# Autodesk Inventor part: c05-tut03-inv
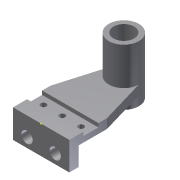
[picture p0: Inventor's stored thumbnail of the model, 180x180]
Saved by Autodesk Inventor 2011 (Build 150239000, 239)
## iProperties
Created: 2010-02
Part Number: c05-tut03-inv
Document SubType Name: Modeling
Designer: CADSoft
Density: 1 g/cm^3
Author: CADSoft
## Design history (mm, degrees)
sketch "Sketch1"
  geometry: 1 further point
sketch "Sketch2"
  geometry: L1 (40, 0)-(40, -10); L2 (10, -30)-(0, -30); L3 (0, -30)-(0, 0); L4 (31, 0)-(31, -4); L5 (31, -4)-(15, -4); L6 (15, -4)-(15, 0); L7 (40, -10)-(10, -10); L8 (10, -10)-(10, -30); L9 (0, 0)-(15, 0); L10 (31, 0)-(40, 0)
  constraints: 20 end point, 1 collinear, 1 horizontal, 1 perpendicular
  dimensions: "d0" = 4 distance of L5.end L6.end; "d1" = 30 distance of L2.end L3.end; "d2" = 15 distance of L3.end L6.end; "d3" = 10 distance of L2.start L2.end; "d4" = 40 distance between parallel lines of L1 L3; "d5" = 16 distance of L4.end L5.end
extrude "Extrusion1" new body sketch "Sketch2" stored distance "d6" = 60; taper "d7" = 0 deg
sketch "Sketch3"
  geometry: L1 (0, 0)-(60, 0) reference; L2 (0, 0)-(14, 48); L3 (14, 48)-(46, 48); L4 (46, 48)-(60, 0); 1 further point
  constraints: 6 end point, 1 equal length
  dimensions: "d8" = 48 distance between parallel lines of L3 L1; "d9" = 32 distance of L2.end L3.end
extrude "Extrusion2" join sketch "Sketch3" distance "d10" = 10; taper "d11" = 0 deg
workplane "Work Plane1"
sketch "Sketch4"
  geometry: L1 (0, 30)-(0, 0) reference; L2 (14, 78)-(46, 78) reference; C1 r 16 at (30, 78); 1 further point
  constraints: 1 centre point, 1 midpoint
  dimensions: "d14" = 32 diameter of C1; "d15" = 30 distance from line of C1.centre L1
extrude "Extrusion3" join sketch "Sketch4" distance "d16" = 60; taper "d17" = 0 deg
sketch "Sketch5"
  geometry: L1 (60, -30)-(60, 0) reference; L2 (0, -30)-(60, -30) reference; C1 r 6 at (15, -20); C2 r 6 at (45, -20); 1 further point
  constraints: 2 centre point, 1 equal radius, 1 horizontal alignment
  dimensions: "d18" = 10 distance from line of L2 C1.centre; "d19" = 30 distance of C2.centre C1.centre; "d20" = 15 distance from line of L1 C2.centre; "d21" = 12 diameter of C1
extrude "Extrusion4" cut sketch "Sketch5" stored distance "d22" = 60; taper "d23" = 0 deg
sketch "Sketch6"
  geometry: L1 (60, -31)-(0, -31) reference; L2 (0, -16)-(0, -31) reference; C1 r 3 at (30, -8.5); C2 r 3 at (10, -8.5); C3 r 3 at (50, -8.5); 1 further point
  constraints: 3 centre point, 2 equal radius, 2 horizontal alignment
  dimensions: "d24" = 6 diameter of C2; "d25" = 22.5 distance from line of L1 C2.centre; "d26" = 10 distance from line of L2 C2.centre; "d27" = 20 distance of C1.centre C2.centre; "d28" = 20 distance of C3.centre C1.centre
extrude "Extrusion5" cut sketch "Sketch6" stored distance "d29" = 60; taper "d30" = 0 deg
sketch "Sketch7"
  geometry: C1 r 16 at (0, 0) reference; C2 r 11 at (0, 0); 1 further point
  constraints: 1 centre point, 1 coincident
  dimensions: "d31" = 22 diameter of C2
extrude "Extrusion6" cut sketch "Sketch7" stored distance "d32" = 60; taper "d33" = 0 deg
body "Solid1"
